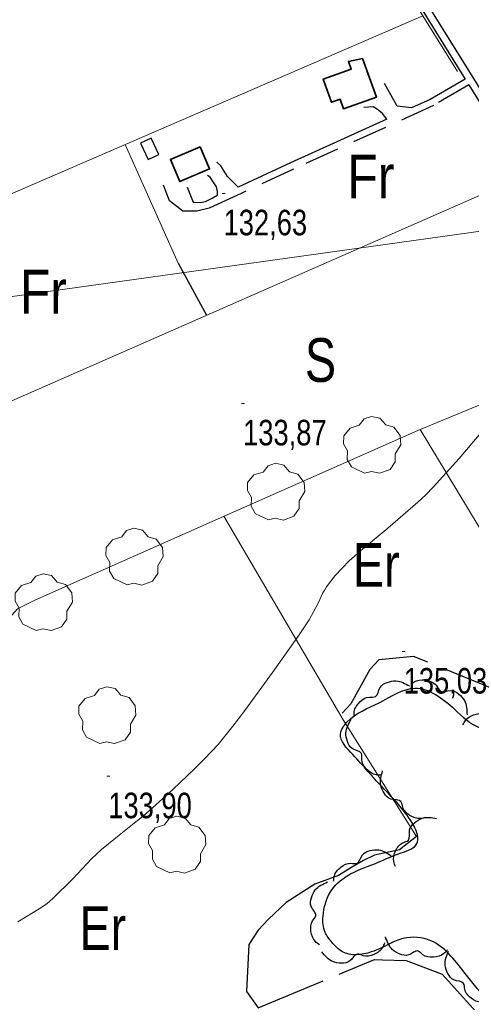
# Model space of a CAD drawing. Extents: x 487425 to 492029, y 4383576 to 4386788.
# Drawn here: x 489030 to 489184.7, y 4384585.2 to 4384922.2 of the extents above; entities that cross this region are included whole.
import ezdxf
from ezdxf.enums import TextEntityAlignment as Align

# ---------------------------------------------------------------- set-up
doc = ezdxf.new("R2010")
doc.units = 0
doc.header["$LTSCALE"] = 4
doc.linetypes.add('LONG_DASHED', pattern=[7.5, 6, -1.5])
doc.linetypes.add('MEDIUM_DASHED', pattern=[4.5, 3, -1.5])
for name, color, linetype, lineweight in [('21', 7, 'Continuous', 25), ('24', 7, 'Continuous', 13), ('25', 7, 'LONG_DASHED', 25), ('27', 7, 'Continuous', 25), ('29', 7, 'Continuous', 13), ('38', 7, 'Continuous', 25), ('47', 7, 'Continuous', 35), ('51', 7, 'Continuous', 13), ('7', 7, 'Continuous', 13), ('9', 7, 'Continuous', 13)]:
    doc.layers.add(name, color=color, linetype=linetype, lineweight=lineweight)
doc.layers.add('31', color=7, linetype='Continuous')

msp = doc.modelspace()

# ---------------------------------------------------------------- linework, layer by layer
at = {"layer": '21'}
msp.add_lwpolyline([(489071.36, 4384879.8), (489074.03, 4384874.23), (489077.69, 4384875.98), (489075.02, 4384881.55)], close=True, dxfattribs=at)
at = {"layer": '24'}
msp.add_lwpolyline([(488954.49, 4384817.11), (489198.5, 4384851.16), (489357.39, 4384873.86), (489601.4, 4384907.91), (489794.34, 4384879.53), (490083.75, 4384822.79), (490248.31, 4384800.09), (490395.85, 4384817.11), (490526.37, 4384822.79), (490764.71, 4384947.63), (491088.16, 4385117.87), (491252.72, 4385202.99), (491256.7, 4385199.2)], dxfattribs=at)
at = {"layer": '25'}
msp.add_line((489084.32, 4384838.69), (489093.94, 4384820.8), dxfattribs=at)
for points in [[(489222.36, 4384690.19), (489212.78, 4384689.59), (489206.03, 4384689.67), (489197.56, 4384690.51), (489164.93, 4384703.86), (489153.06, 4384702.65), (489149.95, 4384699.31), (489143.37, 4384687.6), (489140.48, 4384684.41)], [(489165.88, 4384642.11), (489160.13, 4384637.52), (489151.48, 4384635.75), (489147.71, 4384633.84), (489143.4, 4384631.34), (489139.17, 4384628.76), (489131.11, 4384625.78), (489121.28, 4384619.44), (489115.22, 4384613.73), (489111.72, 4384609.94), (489108.52, 4384605.03), (489107.66, 4384588.98), (489111.72, 4384583.38), (489151.52, 4384599.89), (489154.22, 4384599.85), (489162.32, 4384599.61), (489174.65, 4384594.9), (489195.69, 4384571.62), (489208.75, 4384565.7), (489235.41, 4384528.64)]]:
    msp.add_lwpolyline(points, dxfattribs=at)
at = {"layer": '27'}
for points in [[(489144.54, 4384683.16), (489144.58, 4384684.94), (489146.49, 4384688.22), (489149.77, 4384689.92), (489151.81, 4384690.06), (489153.44, 4384693.22), (489155.89, 4384694.93), (489158.87, 4384695.47), (489163.51, 4384693.71)], [(489164.4, 4384694.63), (489165.94, 4384695.51), (489169.73, 4384695.57), (489172.88, 4384693.63), (489174.06, 4384691.95), (489177.61, 4384692.19), (489180.33, 4384690.97), (489182.32, 4384688.69), (489183.21, 4384683.81)], [(489277.55, 4384599.65), (489253.43, 4384589.57), (489234.85, 4384584.61), (489229.17, 4384580.47), (489221.96, 4384572.75), (489221.7, 4384569.75), (489218.14, 4384566.64), (489212.8, 4384565.88), (489207.48, 4384566.39), (489199.58, 4384570.83), (489195.68, 4384577.18), (489182.16, 4384595.71), (489170.8, 4384606.34), (489161.36, 4384607.13), (489156.68, 4384605.3), (489150.43, 4384602.52), (489140.52, 4384602.56), (489136.88, 4384605.9), (489134.6, 4384609.23), (489133.91, 4384614.79), (489136.48, 4384623.16), (489142.17, 4384628.65), (489151.82, 4384632.89), (489159.74, 4384636.18), (489165.7, 4384639.11), (489160.81, 4384651.84), (489154, 4384659.2), (489144.07, 4384670.19), (489139.87, 4384677.29), (489142.09, 4384681.32), (489153.12, 4384687.94), (489165.33, 4384692.98), (489178.98, 4384685.7), (489187.39, 4384679.53), (489192.78, 4384678.86), (489202.47, 4384679.8), (489219.07, 4384681.64), (489225.29, 4384681.2), (489235.11, 4384673.51), (489252.89, 4384647.05), (489268.53, 4384617.31), (489275.16, 4384606.58), (489277.51, 4384602.05), (489277.33, 4384600.1)], [(489181.81, 4384680.34), (489182.66, 4384681.89), (489185.86, 4384683.94), (489189.55, 4384683.94), (489191.43, 4384683.13), (489194.33, 4384685.19), (489197.29, 4384685.58), (489200.18, 4384684.69), (489203.5, 4384681)], [(489153.86, 4384663.19), (489152.09, 4384663.26), (489148.83, 4384665.2), (489147.17, 4384668.5), (489147.05, 4384670.55), (489143.91, 4384672.22), (489142.24, 4384674.69), (489141.74, 4384677.67), (489143.56, 4384682.29)], [(489169, 4384648.63), (489167.27, 4384648.26), (489163.63, 4384649.33), (489161.21, 4384652.12), (489160.58, 4384654.08), (489157.13, 4384654.92), (489154.89, 4384656.89), (489153.67, 4384659.66), (489154.29, 4384664.58)], [(489158.69, 4384631.82), (489158.12, 4384633.5), (489158.76, 4384637.24), (489161.24, 4384639.97), (489163.11, 4384640.82), (489163.53, 4384644.35), (489165.23, 4384646.81), (489167.83, 4384648.35), (489172.79, 4384648.32)], [(489137.51, 4384626.76), (489137.74, 4384628.52), (489139.97, 4384631.59), (489143.4, 4384632.94), (489145.46, 4384632.87), (489147.4, 4384635.85), (489150.01, 4384637.29), (489153.03, 4384637.52), (489157.46, 4384635.3)], [(489132.66, 4384604.99), (489131.26, 4384606.08), (489129.75, 4384609.56), (489130.32, 4384613.2), (489131.42, 4384614.94), (489129.84, 4384618.13), (489129.92, 4384621.11), (489131.25, 4384623.82), (489135.41, 4384626.52)], [(489176.47, 4384603.25), (489175.28, 4384601.94), (489171.69, 4384600.71), (489168.1, 4384601.57), (489166.46, 4384602.81), (489163.15, 4384601.49), (489160.19, 4384601.8), (489157.59, 4384603.35), (489155.23, 4384607.72)], [(489154.93, 4384605.67), (489154.26, 4384604.03), (489151.32, 4384601.63), (489147.65, 4384601.21), (489145.69, 4384601.8), (489143.04, 4384599.42), (489140.15, 4384598.69), (489137.18, 4384599.24), (489133.46, 4384602.53)], [(489189.84, 4384585.45), (489188.08, 4384585.26), (489184.57, 4384586.7), (489182.44, 4384589.72), (489182.03, 4384591.73), (489178.68, 4384592.92), (489176.66, 4384595.12), (489175.73, 4384598), (489176.84, 4384602.83)]]:
    msp.add_spline(points, degree=3, dxfattribs=at)
at = {"layer": '29'}
for points in [[(489148.15, 4384766.71), (489143.61, 4384768.83), (489142.2, 4384771.37), (489142.3, 4384774.35), (489140.93, 4384776.76), (489140.97, 4384779.51), (489143.13, 4384782.11), (489146.32, 4384783.11), (489147.97, 4384785.3), (489150.54, 4384786.13), (489153.4, 4384785.48), (489155.35, 4384783.21), (489158.16, 4384782.39), (489160.29, 4384779.54), (489160.53, 4384776.41), (489158.65, 4384773.26), (489158.65, 4384770.58), (489156.83, 4384767.97), (489153.21, 4384766.63), (489150.44, 4384767.26)], [(489115.25, 4384750.65), (489110.71, 4384752.77), (489109.3, 4384755.31), (489109.4, 4384758.29), (489108.03, 4384760.7), (489108.07, 4384763.45), (489110.23, 4384766.05), (489113.42, 4384767.05), (489115.07, 4384769.24), (489117.64, 4384770.07), (489120.5, 4384769.42), (489122.45, 4384767.15), (489125.26, 4384766.33), (489127.39, 4384763.48), (489127.63, 4384760.35), (489125.75, 4384757.2), (489125.75, 4384754.52), (489123.93, 4384751.91), (489120.31, 4384750.57), (489117.54, 4384751.2)], [(489066.76, 4384728.4), (489062.22, 4384730.52), (489060.81, 4384733.06), (489060.91, 4384736.04), (489059.54, 4384738.45), (489059.58, 4384741.2), (489061.74, 4384743.8), (489064.93, 4384744.8), (489066.58, 4384746.99), (489069.15, 4384747.82), (489072.01, 4384747.17), (489073.96, 4384744.9), (489076.77, 4384744.08), (489078.9, 4384741.23), (489079.14, 4384738.1), (489077.26, 4384734.95), (489077.26, 4384732.27), (489075.44, 4384729.66), (489071.82, 4384728.32), (489069.05, 4384728.95)], [(489035.67, 4384712.77), (489031.13, 4384714.89), (489029.72, 4384717.43), (489029.82, 4384720.41), (489028.45, 4384722.82), (489028.49, 4384725.57), (489030.65, 4384728.17), (489033.84, 4384729.17), (489035.49, 4384731.36), (489038.06, 4384732.19), (489040.92, 4384731.54), (489042.87, 4384729.27), (489045.68, 4384728.45), (489047.81, 4384725.6), (489048.05, 4384722.47), (489046.17, 4384719.32), (489046.17, 4384716.64), (489044.35, 4384714.03), (489040.73, 4384712.69), (489037.96, 4384713.32)], [(489057.44, 4384674.04), (489052.9, 4384676.16), (489051.49, 4384678.7), (489051.59, 4384681.68), (489050.22, 4384684.09), (489050.26, 4384686.84), (489052.42, 4384689.44), (489055.61, 4384690.44), (489057.26, 4384692.63), (489059.83, 4384693.46), (489062.69, 4384692.81), (489064.64, 4384690.54), (489067.45, 4384689.72), (489069.58, 4384686.87), (489069.82, 4384683.74), (489067.94, 4384680.59), (489067.94, 4384677.91), (489066.12, 4384675.3), (489062.5, 4384673.96), (489059.73, 4384674.59)], [(489081.39, 4384629.65), (489076.85, 4384631.77), (489075.44, 4384634.31), (489075.54, 4384637.29), (489074.17, 4384639.7), (489074.21, 4384642.45), (489076.37, 4384645.05), (489079.56, 4384646.05), (489081.21, 4384648.24), (489083.78, 4384649.07), (489086.64, 4384648.42), (489088.59, 4384646.15), (489091.4, 4384645.33), (489093.53, 4384642.48), (489093.77, 4384639.35), (489091.89, 4384636.2), (489091.89, 4384633.52), (489090.07, 4384630.91), (489086.45, 4384629.57), (489083.68, 4384630.2)]]:
    msp.add_lwpolyline(points, close=True, dxfattribs=at)
at = {"layer": '38'}
msp.add_line((489170.75, 4384925.69), (489194.73, 4384886.93), dxfattribs=at)
for points in [[(489086.73, 4385060.01), (489105.47, 4385029.39), (489128.07, 4384992.16), (489160.17, 4384937.99), (489182.55, 4384901.81)], [(489182.55, 4384901.81), (489170.58, 4384894.79), (489164.24, 4384891.91)], [(489164.24, 4384891.91), (489159.28, 4384892.46), (489154.94, 4384900.31)], [(489183.8, 4384899.8), (489197.37, 4384877.86), (489252.87, 4384783.82), (489276.74, 4384745.66), (489301.69, 4384703.76), (489346.08, 4384629.51), (489370.77, 4384587.28)], [(489155.78, 4384888.06), (489154.3, 4384889.96), (489152.59, 4384891.33), (489151.1, 4384892.25), (489147.87, 4384892.06)], [(489155.78, 4384888.06), (489122.8, 4384873.08), (489104.84, 4384864.72)], [(489104.84, 4384864.72), (489101.16, 4384868.36), (489098.88, 4384871.99), (489097.54, 4384873.35)], [(489087.39, 4384864.69), (489089.14, 4384860.17), (489089.36, 4384859.64), (489089.81, 4384859.56), (489091.98, 4384859.46), (489093.64, 4384859.82), (489095.9, 4384860.92), (489097.64, 4384861.95), (489097.79, 4384862.1), (489097.8, 4384863.15), (489097.44, 4384864.88), (489096.26, 4384866.54), (489095.23, 4384868.13), (489094.34, 4384868.74)], [(489105.84, 4384862.57), (489094.88, 4384857.55), (489090.67, 4384856.55), (489088.72, 4384856.5), (489085.87, 4384856.46), (489081.26, 4384860.04), (489079.22, 4384865.46)]]:
    msp.add_lwpolyline(points, dxfattribs=at)
at = {"layer": '38', "linetype": 'MEDIUM_DASHED'}
msp.add_lwpolyline([(489183.8, 4384899.8), (489171.67, 4384892.68), (489123.79, 4384870.92), (489105.84, 4384862.57)], dxfattribs=at)
at = {"layer": '47'}
for points in [[(489147.46, 4384908.8), (489152.18, 4384895.61), (489140.92, 4384891.6), (489139.74, 4384894.88), (489136.78, 4384893.84), (489133.98, 4384901.77), (489143.55, 4384905.15), (489142.59, 4384907.86)], [(489091.82, 4384878.6), (489081.63, 4384874.26), (489084.86, 4384866.67), (489095.05, 4384871.01)]]:
    msp.add_lwpolyline(points, close=True, dxfattribs=at)
at = {"layer": '51'}
for p, q in [((488964.11, 4384835.23), (489168.09, 4384923.44)), ((489066.12, 4384879.34), (489084.32, 4384838.69)), ((488997.94, 4384778.6), (489201.96, 4384868.29))]:
    msp.add_line(p, q, dxfattribs=at)
for points in [[(489136.36, 4384976.37), (489159.38, 4384937.51), (489179.91, 4384904.34)], [(489236.25, 4384810.18), (489166.41, 4384781.27), (489097.95, 4384751.06), (489041.4, 4384725.82), (489034.99, 4384723.05), (489029.25, 4384720.11), (488992.32, 4384678.89), (488988.14, 4384673.77), (488987.22, 4384672.28), (488986.75, 4384670.86), (488986.18, 4384666.51), (488986, 4384631.03), (488986.04, 4384627.95), (488986.39, 4384625.4), (488986.66, 4384623.37), (489008.55, 4384574.95)], [(489366.62, 4384587.61), (489300.81, 4384560.15), (489167.19, 4384781.6)], [(489099.92, 4384751.93), (489140.75, 4384682.08), (489165.88, 4384642.11)]]:
    msp.add_lwpolyline(points, dxfattribs=at)
at = {"layer": '7'}
for p, q in [((489099.32, 4384862.6), (489100.32, 4384862.6)), ((489106, 4384790.58), (489107, 4384790.58)), ((489161, 4384705.48), (489162, 4384705.48)), ((489059.83, 4384662.74), (489060.83, 4384662.74))]:
    msp.add_line(p, q, dxfattribs=at)
at = {"layer": '9'}
msp.add_lwpolyline([(489029.32, 4384612.83), (489037.28, 4384617.62), (489039.36, 4384619.17), (489041.39, 4384620.82), (489048.25, 4384627.59), (489054.63, 4384634.39), (489056.35, 4384636.05), (489058.05, 4384637.63), (489064.03, 4384642.53), (489070.4, 4384647.54), (489072.36, 4384649.19), (489074.39, 4384650.94), (489082.41, 4384658.2), (489089.99, 4384665.43), (489091.74, 4384667.16), (489093.35, 4384668.78), (489097.94, 4384673.65), (489103, 4384679.94), (489104.92, 4384682.44), (489107.06, 4384685.28), (489116.63, 4384698.31), (489125.73, 4384711.2), (489127.57, 4384713.96), (489129.11, 4384716.36), (489132.24, 4384722.11), (489133.87, 4384725.67), (489134.47, 4384726.69), (489135.13, 4384727.73), (489138.07, 4384731.64), (489142.87, 4384736.56), (489144.71, 4384738.24), (489146.77, 4384740.06), (489156.07, 4384747.78), (489166.36, 4384756.7), (489169.05, 4384759.27), (489171.66, 4384761.88), (489180.51, 4384771.69), (489187.32, 4384779.8)], dxfattribs=at)

# ---------------------------------------------------------------- texts
at = {"layer": '31'}
for s, width, p in [('Fr', 0.85, (489150.27, 4384860.85)), ('Fr', 0.85, (489038.13, 4384821.4)), ('S', 0.8, (489133.02, 4384797.97)), ('Er', 0.8, (489152.13, 4384727.71)), ('Er', 0.8, (489058.48, 4384603.19))]:
    msp.add_text(s, height=15, dxfattribs=dict(at, width=width)).set_placement(p, align=Align.CENTER)
at = {"layer": '7', "width": 0.8}
for s, p in [('132,63', (489099.82, 4384848.23)), ('133,87', (489106.5, 4384776.21)), ('135,03', (489161.5, 4384691.11)), ('133,90', (489060.33, 4384648.37))]:
    msp.add_text(s, height=8.75, dxfattribs=at).set_placement(p)

doc.saveas('drawing.dxf')
